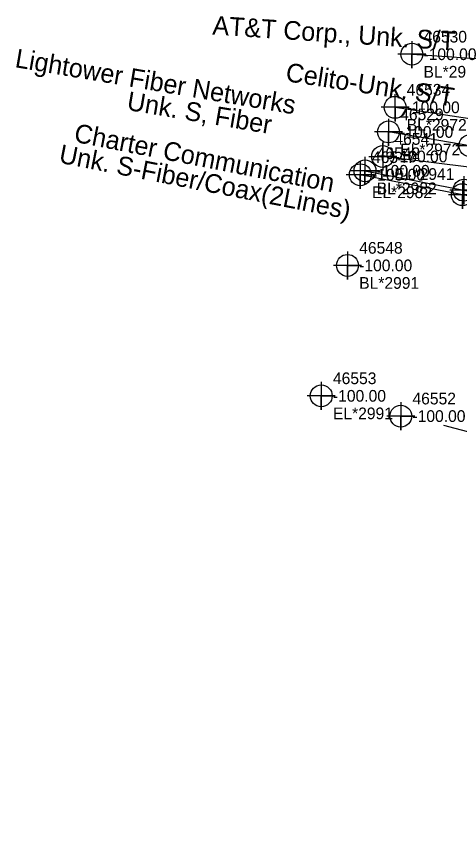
# Model space of a CAD drawing. Extents: x 2083698 to 2094313, y 743246 to 752873.
# Drawn here: x 2093210.3 to 2093305.1, y 743882.5 to 744056.6 of the extents above; entities that cross this region are included whole.
import ezdxf

# ---------------------------------------------------------------- set-up
doc = ezdxf.new("R2010")
doc.units = 0
for name, color, linetype in [('COGO Default Chain', 7, 'Continuous'), ('COGO Default Curve', 7, 'Continuous'), ('COGO Default Point Number', 7, 'Continuous'), ('Exist Property Line', 7, 'Continuous'), ('Exist Right of Way Easement Line', 7, 'Continuous'), ('Exist Right of Way Line', 7, 'Continuous'), ('Exist Right of Way Line Leader', 7, 'Continuous'), ('Exist Right of Way Line Text', 7, 'Continuous'), ('Exist Right of Way Width CELL', 7, 'Continuous'), ('Exist Utilities Gas UG Line SUE LOS B', 7, 'Continuous'), ('Exist Utilities Telephone UG Conduit SUE LOS B', 7, 'Continuous'), ('Exist Utilities Telephone UG Conduit SUE LOS B Text', 7, 'Continuous'), ('Exist Utilities TV UG Cable SUE LOS B', 7, 'Continuous'), ('Exist Utilities TV UG Cable SUE LOS B Text', 7, 'Continuous'), ('Exist Utilities TV UG FO Cable SUE LOS B Cogo Comment', 7, 'Continuous'), ('Exist Utilities TV UG FO Cable SUE LOS B Cogo Elevation', 7, 'Continuous'), ('Exist Utilities TV UG FO Cable SUE LOS B Cogo Number', 7, 'Continuous'), ('Exist Utilities TV UG FO Cable SUE LOS B Cogo Point CELL', 7, 'Continuous'), ('Exist Utilities Water UG Line SUE LOS B', 7, 'Continuous'), ('Old_Level_20', 7, 'Continuous'), ('Scratch_Level_2', 7, 'Continuous'), ('Scratch_Level_3', 7, 'Continuous')]:
    doc.layers.add(name, color=color, linetype=linetype)

msp = doc.modelspace()

# ---------------------------------------------------------------- linework, layer by layer
at = {"layer": 'COGO Default Curve'}
msp.add_lwpolyline([(2093285.6, 744026.66), (2093291.6, 744026.66), (2093288.6, 744026.66), (2093288.6, 744029.66), (2093288.6, 744023.66)], dxfattribs=at)
msp.add_circle((2093288.6, 744026.66), 2.34, dxfattribs=at)
at = {"layer": 'COGO Default Point Number'}
for points in [[(2093281.07, 744006.38), (2093281.07, 744000.38), (2093281.07, 744003.38), (2093284.07, 744003.38), (2093278.07, 744003.38)], [(2093275.46, 743978.5), (2093275.46, 743972.5), (2093275.46, 743975.5), (2093278.46, 743975.5), (2093272.46, 743975.5)], [(2093292.46, 743974.17), (2093292.46, 743968.17), (2093292.46, 743971.17), (2093295.46, 743971.17), (2093289.46, 743971.17)]]:
    msp.add_lwpolyline(points, dxfattribs=at)
for centre in [(2093281.07, 744003.38), (2093275.46, 743975.5), (2093292.46, 743971.17)]:
    msp.add_circle(centre, 2.34, dxfattribs=at)
at = {"layer": 'Exist Right of Way Line Text'}
for points in [[(2093294.81, 744051.33), (2093294.84, 744045.52), (2093294.82, 744048.52), (2093297.84, 744048.52), (2093291.84, 744048.52)], [(2093291.22, 744039.99), (2093291.25, 744034.17), (2093291.23, 744037.17), (2093294.25, 744037.17), (2093288.25, 744037.17)], [(2093289.82, 744034.72), (2093289.85, 744028.91), (2093289.84, 744031.91), (2093292.85, 744031.91), (2093286.85, 744031.91)], [(2093307.23, 744031.78), (2093307.26, 744025.97), (2093307.25, 744028.97), (2093310.26, 744028.97), (2093304.26, 744028.97)]]:
    msp.add_lwpolyline(points, dxfattribs=at)
for centre in [(2093294.84, 744048.52), (2093291.25, 744037.17), (2093289.85, 744031.91), (2093307.26, 744028.97)]:
    msp.add_circle(centre, 2.34, dxfattribs=at)
at = {"layer": 'Exist Utilities Gas UG Line SUE LOS B'}
msp.add_lwpolyline([(2093323.38, 744021.33), (2093321.02, 744022.2), (2093308.13, 744024.21), (2093288.6, 744026.66)], dxfattribs=at)
at = {"layer": 'Exist Utilities Telephone UG Conduit SUE LOS B'}
for points in [[(2093294.82, 744048.52), (2093314, 744047.25), (2093364.93, 744034.23)], [(2093291.23, 744037.17), (2093309.06, 744034.46), (2093328.85, 744032.38), (2093356.83, 744028.23)], [(2093336.37, 744020.74), (2093320.18, 744025.54), (2093307.25, 744028.97), (2093289.84, 744031.91)]]:
    msp.add_lwpolyline(points, dxfattribs=at)
at = {"layer": 'Exist Utilities TV UG Cable SUE LOS B'}
for points in [[(2093284.81, 744023.6), (2093305.96, 744019.44), (2093322.23, 744016.47)], [(2093321.96, 744015.64), (2093305.63, 744018.49), (2093283.81, 744022.76)]]:
    msp.add_lwpolyline(points, dxfattribs=at)
at = {"layer": 'Exist Utilities TV UG FO Cable SUE LOS B Cogo Point CELL'}
for points in [[(2093284.81, 744026.6), (2093284.81, 744020.6), (2093284.81, 744023.6), (2093287.81, 744023.6), (2093281.81, 744023.6)], [(2093283.81, 744025.76), (2093283.81, 744019.76), (2093283.81, 744022.76), (2093286.81, 744022.76), (2093280.81, 744022.76)], [(2093305.63, 744021.49), (2093305.63, 744015.49), (2093305.63, 744018.49), (2093308.63, 744018.49), (2093302.63, 744018.49)], [(2093305.96, 744022.44), (2093305.96, 744016.44), (2093305.96, 744019.44), (2093308.96, 744019.44), (2093302.96, 744019.44)]]:
    msp.add_lwpolyline(points, dxfattribs=at)
for centre in [(2093283.81, 744022.76), (2093284.81, 744023.6), (2093305.96, 744019.44), (2093305.63, 744018.49)]:
    msp.add_circle(centre, 2.34, dxfattribs=at)
at = {"layer": 'Exist Utilities Water UG Line SUE LOS B'}
msp.add_lwpolyline([(2093301.62, 743969.21), (2093335.27, 743960.32), (2093367.08, 743950.37), (2093388.86, 743942.65), (2093404.38, 743937.04), (2093423.81, 743928.99), (2093453.61, 743916.17), (2093475.2, 743907.03), (2093494.4, 743898.43), (2093527.71, 743885.56), (2093539.87, 743878.66), (2093540.83, 743878.08)], dxfattribs=at)

# ---------------------------------------------------------------- texts
at = {"layer": 'COGO Default Chain'}
msp.add_text('-100.00', height=2.5, dxfattribs=at).set_placement((2093291.1, 744025.41))
at = {"layer": 'Exist Property Line'}
for p in [(2093283.57, 744002.13), (2093277.96, 743974.25), (2093294.96, 743969.92)]:
    msp.add_text('-100.00', height=2.5, dxfattribs=at).set_placement(p)
at = {"layer": 'Exist Right of Way Easement Line'}
msp.add_text('EL*2941', height=2.5, dxfattribs=at).set_placement((2093291.1, 744021.66))
at = {"layer": 'Exist Right of Way Line'}
for s, p in [('46548', (2093283.57, 744005.88)), ('46553', (2093277.96, 743978)), ('46552', (2093294.96, 743973.67))]:
    msp.add_text(s, height=2.5, dxfattribs=at).set_placement(p)
at = {"layer": 'Exist Right of Way Line Leader'}
for s, p in [('46530', (2093297.32, 744051.02)), ('46534', (2093293.73, 744039.67)), ('46529', (2093292.34, 744034.41))]:
    msp.add_text(s, height=2.5, dxfattribs=at).set_placement(p)
at = {"layer": 'Exist Right of Way Width CELL'}
for s, p in [('BL*2991', (2093283.57, 743998.38)), ('EL*2991', (2093277.96, 743970.5))]:
    msp.add_text(s, height=2.5, dxfattribs=at).set_placement(p)
at = {"layer": 'Exist Utilities Telephone UG Conduit SUE LOS B Text'}
for s, rotation, p in [('AT&T Corp., Unk. S/T', 356.2214, (2093252.11, 744052.74)), ('Lightower Fiber Networks', 350.4062, (2093209.82, 744045.77)), ('Celito-Unk. S/T', 351.3396, (2093267.68, 744042.78)), ('Unk. S, Fiber', 350.4062, (2093233.72, 744036.65))]:
    msp.add_text(s, height=4, rotation=rotation, dxfattribs=at).set_placement(p)
at = {"layer": 'Exist Utilities TV UG Cable SUE LOS B Text'}
for s, p in [('Charter Communication', (2093222.41, 744029.84)), ('Unk. S-Fiber/Coax(2Lines)', (2093219.19, 744025.36))]:
    msp.add_text(s, height=4, rotation=348.9212, dxfattribs=at).set_placement(p)
at = {"layer": 'Exist Utilities TV UG FO Cable SUE LOS B Cogo Comment'}
for s, p in [('EL*2982', (2093286.31, 744017.76)), ('BL*2982', (2093287.31, 744018.6))]:
    msp.add_text(s, height=2.5, dxfattribs=at).set_placement(p)
at = {"layer": 'Exist Utilities TV UG FO Cable SUE LOS B Cogo Elevation'}
for p in [(2093287.31, 744022.35), (2093286.31, 744021.51)]:
    msp.add_text('-100.00', height=2.5, dxfattribs=at).set_placement(p)
at = {"layer": 'Exist Utilities TV UG FO Cable SUE LOS B Cogo Number'}
for s, p in [('46542', (2093287.31, 744026.1)), ('46547', (2093286.31, 744025.26))]:
    msp.add_text(s, height=2.5, dxfattribs=at).set_placement(p)
at = {"layer": 'Old_Level_20'}
msp.add_text('46541', height=2.5, dxfattribs=at).set_placement((2093291.1, 744029.16))
at = {"layer": 'Scratch_Level_2'}
for p in [(2093297.32, 744047.27), (2093293.73, 744035.92), (2093292.34, 744030.66)]:
    msp.add_text('-100.00', height=2.5, dxfattribs=at).set_placement(p)
at = {"layer": 'Scratch_Level_3'}
for s, p in [('BL*2972', (2093297.32, 744043.52)), ('BL*2972', (2093293.73, 744032.17)), ('EL*2972', (2093292.34, 744026.91))]:
    msp.add_text(s, height=2.5, dxfattribs=at).set_placement(p)

doc.saveas('drawing.dxf')
